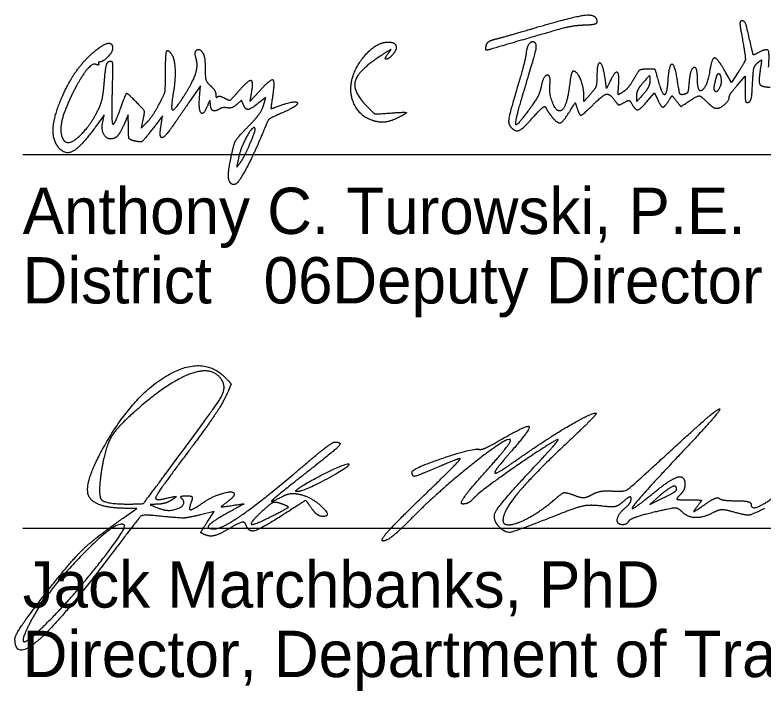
# Model space of a CAD drawing. Extents: x 0 to 34, y 0 to 22.
# Drawn here: x 24.504 to 26.766, y 8.065 to 10.109 of the extents above; entities that cross this region are included whole.
import ezdxf

# ---------------------------------------------------------------- set-up
doc = ezdxf.new("R2010")
doc.units = 0
doc.layers.add('SH_Data', color=7, linetype='Continuous')
doc.layers.add('SH_Text', color=7, linetype='Continuous')

msp = doc.modelspace()

# ---------------------------------------------------------------- linework, layer by layer
at = {"layer": 'SH_Data'}
for p, q in [((24.5279, 9.6868), (28.0279, 9.6868)), ((24.5279, 8.5574), (28.0279, 8.5574))]:
    msp.add_line(p, q, dxfattribs=at)
at = {"layer": 'SH_Text'}
for p, q in [((25.9287, 10.0152), (25.9287, 10.0152)), ((25.5689, 9.7969), (25.5689, 9.7969)), ((25.2156, 9.7211), (25.2156, 9.7211)), ((25.157, 9.6001), (25.157, 9.6001)), ((24.9902, 8.7624), (24.9902, 8.7624)), ((25.3555, 8.6726), (25.3555, 8.6726)), ((26.5045, 8.6746), (26.5045, 8.6746)), ((25.7273, 8.6436), (25.7273, 8.6436)), ((25.3107, 8.6309), (25.3107, 8.6309))]:
    msp.add_line(p, q, dxfattribs=at)
for points in [[(26.6905, 9.9359), (26.6698, 9.9047), (26.6524, 9.9358)], [(26.3033, 9.9091), (26.2923, 9.8869), (26.2879, 9.9183)], [(26.6875, 9.8961), (26.7115, 9.9235), (26.7115, 9.8825)], [(25.0623, 9.8595), (25.0648, 9.8949), (25.032, 9.8469)], [(25.2187, 9.8726), (25.2144, 9.8469), (25.2425, 9.8777)], [(25.2556, 9.8352), (25.2625, 9.8593), (25.2419, 9.8431)], [(26.2437, 9.8693), (26.224, 9.8469), (26.2237, 9.8693)], [(26.4178, 9.8503), (26.4375, 9.8737), (26.4463, 9.8543)], [(24.7697, 9.7845), (24.774, 9.8066), (24.757, 9.7827)], [(24.8473, 9.7698), (24.8471, 9.8069), (24.8322, 9.7741)], [(24.8914, 9.7932), (24.8859, 9.7669), (24.902, 9.7829)], [(24.946, 9.7755), (24.9507, 9.8041), (24.9233, 9.7682)], [(26.4527, 8.6549), (26.4232, 8.6293), (26.4638, 8.649)], [(24.8425, 8.5955), (24.8732, 8.6167), (24.8354, 8.6174)], [(25.0855, 8.5756), (25.1067, 8.608), (25.0649, 8.5979)]]:
    msp.add_lwpolyline(points, dxfattribs=at)
for points in [[(26.0677, 10.0674), (26.1931, 10.1047), (26.2635, 10.1121), (26.2635, 10.088)], [(26.2635, 10.088), (26.2635, 10.0826), (26.2477, 10.0784), (26.2253, 10.0778)], [(26.7022, 10.0909), (26.6963, 10.0909), (26.6954, 10.0798), (26.6995, 10.0569)], [(26.7309, 10.0087), (26.7165, 10.0725), (26.7101, 10.0909), (26.7022, 10.0909)], [(26.2253, 10.0778), (26.1933, 10.0768), (26.1405, 10.0633), (25.9407, 10.0049)], [(25.9595, 10.0367), (25.9749, 10.0405), (26.0236, 10.0543), (26.0677, 10.0674)], [(26.6995, 10.0569), (26.7128, 9.982), (26.7117, 9.9681), (26.6905, 9.9359)], [(24.7437, 9.9978), (24.7705, 10.0204), (24.7995, 10.0257), (24.7995, 10.0081)], [(25.5197, 9.8846), (25.5201, 9.9336), (25.5945, 10.0269), (25.6332, 10.0269)], [(25.6332, 10.0269), (25.6521, 10.0269), (25.6602, 10.0062), (25.6474, 9.9908)], [(25.9287, 10.0152), (25.9304, 10.0243), (25.9422, 10.0325), (25.9595, 10.0367)], [(26.039, 9.8651), (26.0736, 9.9806), (26.0827, 10.0183), (26.0773, 10.0237)], [(26.0773, 10.0237), (26.0685, 10.0325), (26.0512, 10.0135), (26.0495, 9.9933)], [(24.6396, 9.8432), (24.6598, 9.8945), (24.7107, 9.9701), (24.7437, 9.9978)], [(24.7995, 10.0081), (24.7995, 9.9975), (24.7707, 9.9669), (24.7606, 9.9669)], [(24.9595, 9.9344), (24.9595, 9.9904), (24.9665, 10.0079), (24.9801, 9.986)], [(25.0516, 9.9786), (25.0458, 9.9969), (25.0625, 10.0093), (25.0723, 9.9939)], [(25.6325, 9.9928), (25.6421, 10.0049), (25.6405, 10.0047), (25.6195, 9.9915)], [(25.9407, 10.0049), (25.9295, 10.0017), (25.9266, 10.0042), (25.9287, 10.0152)], [(26.7525, 9.9955), (26.7378, 9.9876), (26.7353, 9.9891), (26.7309, 10.0087)], [(26.7823, 9.9512), (26.7857, 9.9948), (26.7766, 10.0084), (26.7525, 9.9955)], [(24.9801, 9.986), (24.9876, 9.9738), (24.9892, 9.9095), (24.983, 9.8735)], [(25.015, 9.8634), (25.0431, 9.9078), (25.0586, 9.9565), (25.0516, 9.9786)], [(25.0723, 9.9939), (25.0761, 9.9879), (25.0793, 9.9664), (25.0794, 9.9461)], [(25.6195, 9.9915), (25.5442, 9.9439), (25.5228, 9.8784), (25.5678, 9.8333)], [(25.6474, 9.9908), (25.6335, 9.974), (25.6192, 9.9759), (25.6325, 9.9928)], [(26.0495, 9.9933), (26.0487, 9.983), (26.0371, 9.9379), (26.0237, 9.893)], [(26.6524, 9.9358), (26.629, 9.9776), (26.6111, 9.9802), (26.605, 9.9426)], [(26.7492, 9.9642), (26.7609, 9.9738), (26.7616, 9.9718), (26.7571, 9.9434)], [(24.7485, 9.9596), (24.7359, 9.9645), (24.6881, 9.8962), (24.6629, 9.8376)], [(24.7574, 9.9612), (24.7584, 9.958), (24.7544, 9.9573), (24.7485, 9.9596)], [(24.7606, 9.9669), (24.7578, 9.9669), (24.7563, 9.9643), (24.7574, 9.9612)], [(24.775, 9.9103), (24.7778, 9.9455), (24.7833, 9.9669), (24.79, 9.9691)], [(24.79, 9.9691), (24.7983, 9.9718), (24.7999, 9.9528), (24.798, 9.8757)], [(26.2879, 9.9183), (26.2818, 9.9617), (26.2635, 9.966), (26.2635, 9.924)], [(26.5075, 9.9065), (26.5005, 9.9575), (26.4815, 9.962), (26.4779, 9.9135)], [(26.5675, 9.9149), (26.5675, 9.9543), (26.5449, 9.9455), (26.5419, 9.905)], [(26.7338, 9.9008), (26.7355, 9.9375), (26.7401, 9.9568), (26.7492, 9.9642)], [(24.9388, 9.8364), (24.9559, 9.8675), (24.9595, 9.8844), (24.9595, 9.9344)], [(25.0794, 9.9461), (25.0795, 9.9196), (25.084, 9.9053), (25.0955, 9.8949)], [(26.1212, 9.8972), (26.1245, 9.929), (26.1015, 9.9254), (26.0949, 9.8931)], [(26.1924, 9.9389), (26.1887, 9.9389), (26.1837, 9.9216), (26.1812, 9.9005)], [(26.2237, 9.8693), (26.2235, 9.8937), (26.2031, 9.9389), (26.1924, 9.9389)], [(26.3291, 9.8957), (26.332, 9.9319), (26.3181, 9.9391), (26.3033, 9.9091)], [(26.4155, 9.9451), (26.3961, 9.9446), (26.3878, 9.9385), (26.3747, 9.9152)], [(26.4493, 9.9103), (26.4407, 9.9427), (26.4377, 9.9458), (26.4155, 9.9451)], [(26.605, 9.9426), (26.5969, 9.8929), (26.5675, 9.8711), (26.5675, 9.9149)], [(26.6205, 9.9049), (26.6234, 9.917), (26.6269, 9.9283), (26.6284, 9.93)], [(26.6284, 9.93), (26.634, 9.9366), (26.641, 9.9064), (26.6366, 9.8949)], [(26.7571, 9.9434), (26.7513, 9.9073), (26.7608, 9.8909), (26.7876, 9.8909)], [(24.7618, 9.8349), (24.7666, 9.8459), (24.7725, 9.8798), (24.775, 9.9103)], [(25.1806, 9.8785), (25.2101, 9.9125), (25.225, 9.9102), (25.2187, 9.8726)], [(25.2425, 9.8777), (25.2773, 9.9159), (25.2902, 9.9105), (25.2828, 9.8609)], [(26.2635, 9.924), (26.2635, 9.9011), (26.2578, 9.8853), (26.2437, 9.8693)], [(26.3747, 9.9152), (26.3657, 9.8991), (26.3512, 9.8816), (26.3425, 9.8761)], [(26.3837, 9.8644), (26.3836, 9.8741), (26.3924, 9.8921), (26.4032, 9.9044)], [(26.4032, 9.9044), (26.4221, 9.9259), (26.423, 9.9261), (26.4232, 9.9093)], [(26.4232, 9.9093), (26.4234, 9.8997), (26.4146, 9.8817), (26.4037, 9.8693)], [(26.4779, 9.9135), (26.4746, 9.8684), (26.461, 9.8669), (26.4493, 9.9103)], [(26.5263, 9.8685), (26.516, 9.8666), (26.5119, 9.8749), (26.5075, 9.9065)], [(26.5419, 9.905), (26.5402, 9.8811), (26.5356, 9.8703), (26.5263, 9.8685)], [(26.6366, 9.8949), (26.6283, 9.8733), (26.6149, 9.8816), (26.6205, 9.9049)], [(25.0955, 9.8949), (25.1043, 9.8869), (25.1115, 9.875), (25.1115, 9.8683)], [(25.5689, 9.7969), (25.5476, 9.8072), (25.5194, 9.8574), (25.5197, 9.8846)], [(26.0237, 9.893), (25.9997, 9.812), (25.9946, 9.7785), (26.0048, 9.7682)], [(26.0949, 9.8931), (26.092, 9.8789), (26.0839, 9.8591), (26.0769, 9.8491)], [(26.1498, 9.8189), (26.1386, 9.8189), (26.1187, 9.8733), (26.1212, 9.8972)], [(26.1812, 9.9005), (26.1762, 9.8585), (26.161, 9.8189), (26.1498, 9.8189)], [(26.3425, 9.8761), (26.3277, 9.8669), (26.3269, 9.8682), (26.3291, 9.8957)], [(26.6635, 9.8611), (26.6635, 9.8653), (26.6743, 9.8811), (26.6875, 9.8961)], [(26.7115, 9.8825), (26.7115, 9.8533), (26.7144, 9.8425), (26.7215, 9.8449)], [(26.7215, 9.8449), (26.7278, 9.847), (26.7324, 9.8676), (26.7338, 9.9008)], [(24.798, 9.8757), (24.7966, 9.8224), (24.7979, 9.7789), (24.8008, 9.7789)], [(24.8201, 9.8169), (24.8401, 9.8712), (24.8441, 9.8734), (24.8721, 9.8447)], [(24.983, 9.8735), (24.9743, 9.8239), (24.9874, 9.8198), (25.015, 9.8634)], [(25.087, 9.8362), (25.0747, 9.8055), (25.0596, 9.8198), (25.0623, 9.8595)], [(25.1115, 9.8683), (25.1115, 9.8617), (25.1138, 9.8585), (25.1165, 9.8613)], [(25.1165, 9.8613), (25.1193, 9.8641), (25.1291, 9.8623), (25.1382, 9.8575)], [(25.1382, 9.8575), (25.1526, 9.8498), (25.1582, 9.8526), (25.1806, 9.8785)], [(25.2828, 9.8609), (25.2779, 9.8283), (25.2788, 9.8249), (25.2911, 9.8297)], [(26.0769, 9.8491), (26.0249, 9.7744), (26.0132, 9.7793), (26.039, 9.8651)], [(26.2518, 9.8376), (26.2818, 9.8676), (26.3025, 9.8713), (26.318, 9.8496)], [(26.4037, 9.8693), (26.3849, 9.8479), (26.384, 9.8477), (26.3837, 9.8644)], [(26.4808, 9.8501), (26.49, 9.8648), (26.4907, 9.8648), (26.5039, 9.8485)], [(26.5405, 9.8471), (26.5671, 9.8648), (26.5784, 9.8639), (26.5999, 9.8424)], [(26.6249, 9.8269), (26.6366, 9.8269), (26.6635, 9.8507), (26.6635, 9.8611)], [(24.6342, 9.7112), (24.6185, 9.7327), (24.6211, 9.7963), (24.6396, 9.8432)], [(24.6629, 9.8376), (24.6464, 9.7991), (24.6408, 9.7482), (24.6511, 9.7315)], [(24.8721, 9.8447), (24.8933, 9.8231), (24.8961, 9.8156), (24.8914, 9.7932)], [(24.902, 9.7829), (24.9109, 9.7917), (24.9275, 9.8158), (24.9388, 9.8364)], [(25.032, 9.8469), (25.0139, 9.8205), (24.9911, 9.7873), (24.9813, 9.7732)], [(25.095, 9.8414), (25.0946, 9.8508), (25.0922, 9.8493), (25.087, 9.8362)], [(25.1215, 9.8242), (25.1084, 9.816), (25.0956, 9.8243), (25.095, 9.8414)], [(25.1752, 9.8386), (25.1673, 9.8315), (25.1542, 9.8267), (25.1462, 9.8281)], [(25.1942, 9.8392), (25.19, 9.8503), (25.188, 9.8502), (25.1752, 9.8386)], [(25.2419, 9.8431), (25.2173, 9.8237), (25.2007, 9.8224), (25.1942, 9.8392)], [(25.2911, 9.8297), (25.3506, 9.8525), (25.365, 9.8355), (25.3071, 9.8107)], [(26.1826, 9.8194), (26.197, 9.843), (26.1982, 9.8435), (26.2032, 9.8277)], [(26.2032, 9.8277), (26.2106, 9.8045), (26.2208, 9.8066), (26.2518, 9.8376)], [(26.318, 9.8496), (26.3265, 9.8376), (26.3315, 9.8365), (26.3451, 9.8438)], [(26.3451, 9.8438), (26.3585, 9.8509), (26.3633, 9.8502), (26.3691, 9.8398)], [(26.3691, 9.8398), (26.3798, 9.8206), (26.3957, 9.8241), (26.4178, 9.8503)], [(26.4463, 9.8543), (26.4569, 9.831), (26.4681, 9.8296), (26.4808, 9.8501)], [(26.5039, 9.8485), (26.5173, 9.8318), (26.5176, 9.8318), (26.5405, 9.8471)], [(26.5999, 9.8424), (26.6085, 9.8339), (26.6197, 9.8269), (26.6249, 9.8269)], [(24.6511, 9.7315), (24.6644, 9.71), (24.7369, 9.7778), (24.7618, 9.8349)], [(24.8008, 9.7789), (24.8038, 9.7789), (24.8125, 9.796), (24.8201, 9.8169)], [(25.1462, 9.8281), (25.1381, 9.8294), (25.127, 9.8277), (25.1215, 9.8242)], [(25.2086, 9.7705), (25.2307, 9.7929), (25.2518, 9.822), (25.2556, 9.8352)], [(25.5678, 9.8333), (25.5906, 9.8106), (25.5952, 9.8092), (25.6398, 9.8125)], [(25.6398, 9.8125), (25.666, 9.8144), (25.6875, 9.8149), (25.6875, 9.8136)], [(25.6875, 9.8136), (25.6875, 9.8123), (25.6769, 9.8058), (25.6639, 9.7991)], [(26.0719, 9.8009), (26.0918, 9.8232), (26.1072, 9.8348), (26.1092, 9.829)], [(26.1092, 9.829), (26.1112, 9.8236), (26.1191, 9.8113), (26.1269, 9.8017)], [(26.1269, 9.8017), (26.1444, 9.78), (26.1621, 9.7856), (26.1826, 9.8194)], [(25.3071, 9.8107), (25.2757, 9.7972), (25.2684, 9.7894), (25.2535, 9.753)], [(25.6639, 9.7991), (25.6366, 9.785), (25.5956, 9.7841), (25.5689, 9.7969)], [(26.0048, 9.7682), (26.0182, 9.7549), (26.0408, 9.7659), (26.0719, 9.8009)], [(24.757, 9.7827), (24.7073, 9.7129), (24.6552, 9.6826), (24.6342, 9.7112)], [(24.8052, 9.7366), (24.7863, 9.7294), (24.7648, 9.7585), (24.7697, 9.7845)], [(24.8322, 9.7741), (24.8241, 9.7561), (24.8119, 9.7392), (24.8052, 9.7366)], [(24.8615, 9.7291), (24.8507, 9.7319), (24.8474, 9.7413), (24.8473, 9.7698)], [(24.9233, 9.7682), (24.894, 9.7299), (24.8837, 9.7234), (24.8615, 9.7291)], [(24.9813, 9.7732), (24.9565, 9.7374), (24.94, 9.7385), (24.946, 9.7755)], [(25.16, 9.69), (25.1667, 9.7211), (25.1773, 9.7387), (25.2086, 9.7705)], [(25.2295, 9.7675), (25.2229, 9.7742), (25.1859, 9.7054), (25.1798, 9.6749)], [(25.2535, 9.753), (25.2283, 9.6913), (25.1799, 9.6004), (25.1705, 9.5972)], [(25.2156, 9.7211), (25.2255, 9.7444), (25.2318, 9.7652), (25.2295, 9.7675)], [(25.1858, 9.6629), (25.1922, 9.6717), (25.2056, 9.6979), (25.2156, 9.7211)], [(25.157, 9.6001), (25.149, 9.608), (25.1502, 9.6443), (25.16, 9.69)], [(25.1798, 9.6749), (25.1745, 9.6489), (25.175, 9.6481), (25.1858, 9.6629)], [(25.1705, 9.5972), (25.1661, 9.5958), (25.16, 9.597), (25.157, 9.6001)], [(24.7789, 8.8132), (24.8651, 8.9636), (25.0732, 9.0796), (25.1389, 9.0139)], [(25.1299, 9.0048), (25.104, 9.0468), (24.9779, 9.0056), (24.8825, 8.924)], [(24.9902, 8.7624), (25.1115, 8.9259), (25.144, 8.9821), (25.1299, 9.0048)], [(25.1389, 9.0139), (25.1577, 8.9952), (25.1577, 8.9901), (25.1394, 8.9517)], [(25.1394, 8.9517), (25.1284, 8.9287), (25.0767, 8.8532), (25.0245, 8.7838)], [(24.8825, 8.924), (24.8159, 8.867), (24.7771, 8.8028), (24.766, 8.7316)], [(26.4869, 8.7921), (26.5619, 8.8612), (26.6279, 8.9178), (26.6336, 8.9179)], [(26.6336, 8.9179), (26.6394, 8.918), (26.5873, 8.8578), (26.518, 8.7842)], [(26.0326, 8.7717), (26.1131, 8.8283), (26.2445, 8.9055), (26.2602, 8.9055)], [(26.2602, 8.9055), (26.265, 8.9055), (26.2237, 8.8629), (26.1684, 8.8108)], [(25.9736, 8.8252), (26.0524, 8.8713), (26.0646, 8.8581), (26.0054, 8.7908)], [(26.0017, 8.8249), (25.9921, 8.8346), (25.7824, 8.6676), (25.7045, 8.5883)], [(26.142, 8.8245), (26.0929, 8.7967), (25.9046, 8.6645), (25.8914, 8.6485)], [(25.908, 8.796), (25.9136, 8.7941), (25.9431, 8.8073), (25.9736, 8.8252)], [(25.9239, 8.7246), (25.9702, 8.7763), (26.0052, 8.8215), (26.0017, 8.8249)], [(26.0768, 8.7456), (26.123, 8.7948), (26.1523, 8.8303), (26.142, 8.8245)], [(24.8354, 8.6174), (24.7375, 8.6191), (24.7141, 8.7002), (24.7789, 8.8132)], [(25.369, 8.7397), (25.4194, 8.7826), (25.4649, 8.8177), (25.4701, 8.8178)], [(25.4701, 8.8178), (25.495, 8.8183), (25.4716, 8.7928), (25.3857, 8.7255)], [(25.7047, 8.7274), (25.7049, 8.7379), (25.8923, 8.8011), (25.908, 8.796)], [(26.1684, 8.8108), (26.0687, 8.7171), (25.9795, 8.6089), (25.9795, 8.582)], [(25.0245, 8.7838), (24.9722, 8.7144), (24.9295, 8.6538), (24.9295, 8.649)], [(26.0054, 8.7908), (25.9774, 8.759), (25.9545, 8.7293), (25.9545, 8.7249)], [(26.3119, 8.6697), (26.3453, 8.6669), (26.3688, 8.6833), (26.4869, 8.7921)], [(26.518, 8.7842), (26.3885, 8.6467), (26.3564, 8.5994), (26.4386, 8.6671)], [(24.844, 8.6305), (24.8907, 8.6305), (24.8953, 8.6346), (24.9902, 8.7624)], [(25.3555, 8.6726), (25.3759, 8.6904), (25.5079, 8.7562), (25.5131, 8.7511)], [(25.5131, 8.7511), (25.5193, 8.7449), (25.3767, 8.668), (25.359, 8.668)], [(25.7273, 8.6436), (25.7983, 8.712), (25.8537, 8.768), (25.8502, 8.768)], [(25.8502, 8.768), (25.8468, 8.768), (25.8178, 8.7568), (25.7857, 8.743)], [(25.9545, 8.7249), (25.9545, 8.7204), (25.9896, 8.7415), (26.0326, 8.7717)], [(24.766, 8.7316), (24.7545, 8.6582), (24.776, 8.6305), (24.844, 8.6305)], [(25.1076, 8.5555), (25.1307, 8.5555), (25.2567, 8.6443), (25.369, 8.7397)], [(25.7857, 8.743), (25.7231, 8.7162), (25.7044, 8.7126), (25.7047, 8.7274)], [(25.9697, 8.5599), (25.9445, 8.5851), (25.9734, 8.6352), (26.0768, 8.7456)], [(26.7295, 8.629), (26.7295, 8.6062), (26.8248, 8.6676), (26.8951, 8.7358)], [(25.3857, 8.7255), (25.2925, 8.6525), (25.271, 8.6309), (25.315, 8.6544)], [(25.8581, 8.6305), (25.8478, 8.6305), (25.8767, 8.6718), (25.9239, 8.7246)], [(26.4386, 8.6671), (26.487, 8.707), (26.5295, 8.7174), (26.5295, 8.6893)], [(26.5045, 8.6746), (26.5045, 8.6881), (26.4804, 8.6789), (26.4527, 8.6549)], [(26.5295, 8.6893), (26.5295, 8.6803), (26.5227, 8.6663), (26.5145, 8.658)], [(25.0736, 8.6349), (25.1025, 8.6547), (25.167, 8.6722), (25.167, 8.6603)], [(25.167, 8.6603), (25.167, 8.6557), (25.1572, 8.6449), (25.1453, 8.6362)], [(25.315, 8.6544), (25.3276, 8.6612), (25.3515, 8.6633), (25.3681, 8.6591)], [(25.359, 8.668), (25.3542, 8.668), (25.3526, 8.6701), (25.3555, 8.6726)], [(26.137, 8.6455), (26.1573, 8.6636), (26.1701, 8.6662), (26.1939, 8.6572)], [(26.2489, 8.6592), (26.2623, 8.6668), (26.2906, 8.6715), (26.3119, 8.6697)], [(26.4638, 8.649), (26.4862, 8.6598), (26.5045, 8.6713), (26.5045, 8.6746)], [(24.9295, 8.649), (24.9295, 8.6442), (24.9449, 8.6439), (24.9638, 8.6483)], [(24.9795, 8.6436), (24.9692, 8.6366), (24.9495, 8.6305), (24.9357, 8.6299)], [(24.9399, 8.6173), (24.9698, 8.6053), (25.026, 8.6298), (25.0086, 8.6473)], [(24.9638, 8.6483), (24.9894, 8.6542), (24.9934, 8.653), (24.9795, 8.6436)], [(25.0086, 8.6473), (25.004, 8.6518), (25.0103, 8.6555), (25.0225, 8.6555)], [(25.0225, 8.6555), (25.037, 8.6555), (25.0422, 8.6491), (25.0375, 8.6368)], [(25.4011, 8.6177), (25.3843, 8.6418), (25.3822, 8.6413), (25.3165, 8.5989)], [(25.3681, 8.6591), (25.4042, 8.6499), (25.4625, 8.593), (25.4358, 8.593)], [(25.617, 8.5187), (25.6067, 8.5189), (25.6563, 8.5751), (25.7273, 8.6436)], [(25.8914, 8.6485), (25.8831, 8.6386), (25.8682, 8.6305), (25.8581, 8.6305)], [(25.9975, 8.568), (26.0192, 8.568), (26.1006, 8.6132), (26.137, 8.6455)], [(26.1939, 8.6572), (26.2141, 8.6495), (26.2329, 8.6502), (26.2489, 8.6592)], [(26.3444, 8.639), (26.3287, 8.6248), (26.3075, 8.6204), (26.2749, 8.6246)], [(26.367, 8.6465), (26.367, 8.6536), (26.3568, 8.6502), (26.3444, 8.639)], [(26.3482, 8.618), (26.3585, 8.6266), (26.367, 8.6394), (26.367, 8.6465)], [(26.5145, 8.658), (26.5028, 8.6464), (26.5087, 8.643), (26.541, 8.643)], [(26.541, 8.643), (26.5785, 8.643), (26.5809, 8.641), (26.5654, 8.6216)], [(26.5871, 8.6275), (26.6085, 8.6425), (26.6293, 8.6516), (26.6332, 8.6477)], [(26.6332, 8.6477), (26.6371, 8.6437), (26.6604, 8.6405), (26.6849, 8.6405)], [(26.6849, 8.6405), (26.7094, 8.6405), (26.7295, 8.6353), (26.7295, 8.629)], [(24.9357, 8.6299), (24.9133, 8.629), (24.9138, 8.6277), (24.9399, 8.6173)], [(25.0375, 8.6368), (25.0285, 8.6135), (25.0414, 8.6129), (25.0736, 8.6349)], [(25.1453, 8.6362), (25.1264, 8.6224), (25.1284, 8.6211), (25.161, 8.626)], [(25.161, 8.626), (25.1977, 8.6316), (25.1976, 8.6313), (25.1522, 8.6062)], [(25.3107, 8.6309), (25.2935, 8.6373), (25.277, 8.6321), (25.2576, 8.6144)], [(25.2826, 8.5946), (25.329, 8.6183), (25.3325, 8.6229), (25.3107, 8.6309)], [(25.4358, 8.593), (25.4262, 8.593), (25.4106, 8.6041), (25.4011, 8.6177)], [(26.2749, 8.6246), (26.2457, 8.6283), (26.2058, 8.6218), (26.1693, 8.6074)], [(26.3412, 8.568), (26.3229, 8.568), (26.3274, 8.6008), (26.3482, 8.618)], [(26.5199, 8.6076), (26.5088, 8.6187), (26.4887, 8.6182), (26.4355, 8.6055)], [(26.5654, 8.6216), (26.5533, 8.6066), (26.5598, 8.6084), (26.5871, 8.6275)], [(26.7698, 8.6165), (26.7324, 8.598), (26.7138, 8.5957), (26.6807, 8.6052)], [(24.5916, 8.3533), (24.6692, 8.4538), (24.7493, 8.5311), (24.8425, 8.5955)], [(24.9237, 8.5956), (24.8903, 8.5989), (24.8786, 8.5884), (24.8019, 8.4868)], [(25.0649, 8.5979), (25.0246, 8.5882), (25.0023, 8.5878), (24.9237, 8.5956)], [(25.1522, 8.6062), (25.1011, 8.578), (25.0814, 8.5555), (25.1076, 8.5555)], [(25.3165, 8.5989), (25.2476, 8.5546), (25.2101, 8.5448), (25.202, 8.5692)], [(25.2576, 8.6144), (25.2133, 8.5739), (25.2246, 8.565), (25.2826, 8.5946)], [(26.1693, 8.6074), (26.0233, 8.5497), (25.9882, 8.5414), (25.9697, 8.5599)], [(26.4355, 8.6055), (26.3972, 8.5963), (26.3629, 8.5841), (26.3594, 8.5784)], [(26.6162, 8.6051), (26.5854, 8.5887), (26.5376, 8.5899), (26.5199, 8.6076)], [(26.6807, 8.6052), (26.6538, 8.6129), (26.6307, 8.6129), (26.6162, 8.6051)], [(24.8354, 8.5663), (24.8145, 8.5872), (24.596, 8.3615), (24.5497, 8.2712)], [(25.0843, 8.5356), (25.0661, 8.5426), (25.0662, 8.5462), (25.0855, 8.5756)], [(25.202, 8.5692), (25.1991, 8.5778), (25.1799, 8.5726), (25.1508, 8.5554)], [(25.7045, 8.5883), (25.6667, 8.5499), (25.6273, 8.5185), (25.617, 8.5187)], [(25.9795, 8.582), (25.9795, 8.5743), (25.9876, 8.568), (25.9975, 8.568)], [(26.3594, 8.5784), (26.3559, 8.5727), (26.3477, 8.568), (26.3412, 8.568)], [(24.6198, 8.2899), (24.6874, 8.359), (24.8431, 8.5586), (24.8354, 8.5663)], [(25.1508, 8.5554), (25.1252, 8.5403), (25.0953, 8.5314), (25.0843, 8.5356)], [(24.8019, 8.4868), (24.6496, 8.2847), (24.5045, 8.156), (24.5045, 8.223)], [(24.5045, 8.223), (24.5045, 8.2327), (24.5437, 8.2913), (24.5916, 8.3533)], [(24.5497, 8.2712), (24.5184, 8.2102), (24.55, 8.2187), (24.6198, 8.2899)]]:
    msp.add_open_spline(points, degree=2, dxfattribs=at)

# ---------------------------------------------------------------- texts
for s, p in [('Anthony C. Turowski, P.E.', (24.5279, 9.4468)), ('District       Deputy Director', (24.5279, 9.2368)), ('              06', (24.5279, 9.2368)), ('Jack Marchbanks, PhD', (24.5279, 8.3174)), ('Director, Department of Transportation', (24.5279, 8.1074))]:
    msp.add_text(s, height=0.14, dxfattribs=at).set_placement(p)

doc.saveas('drawing.dxf')
